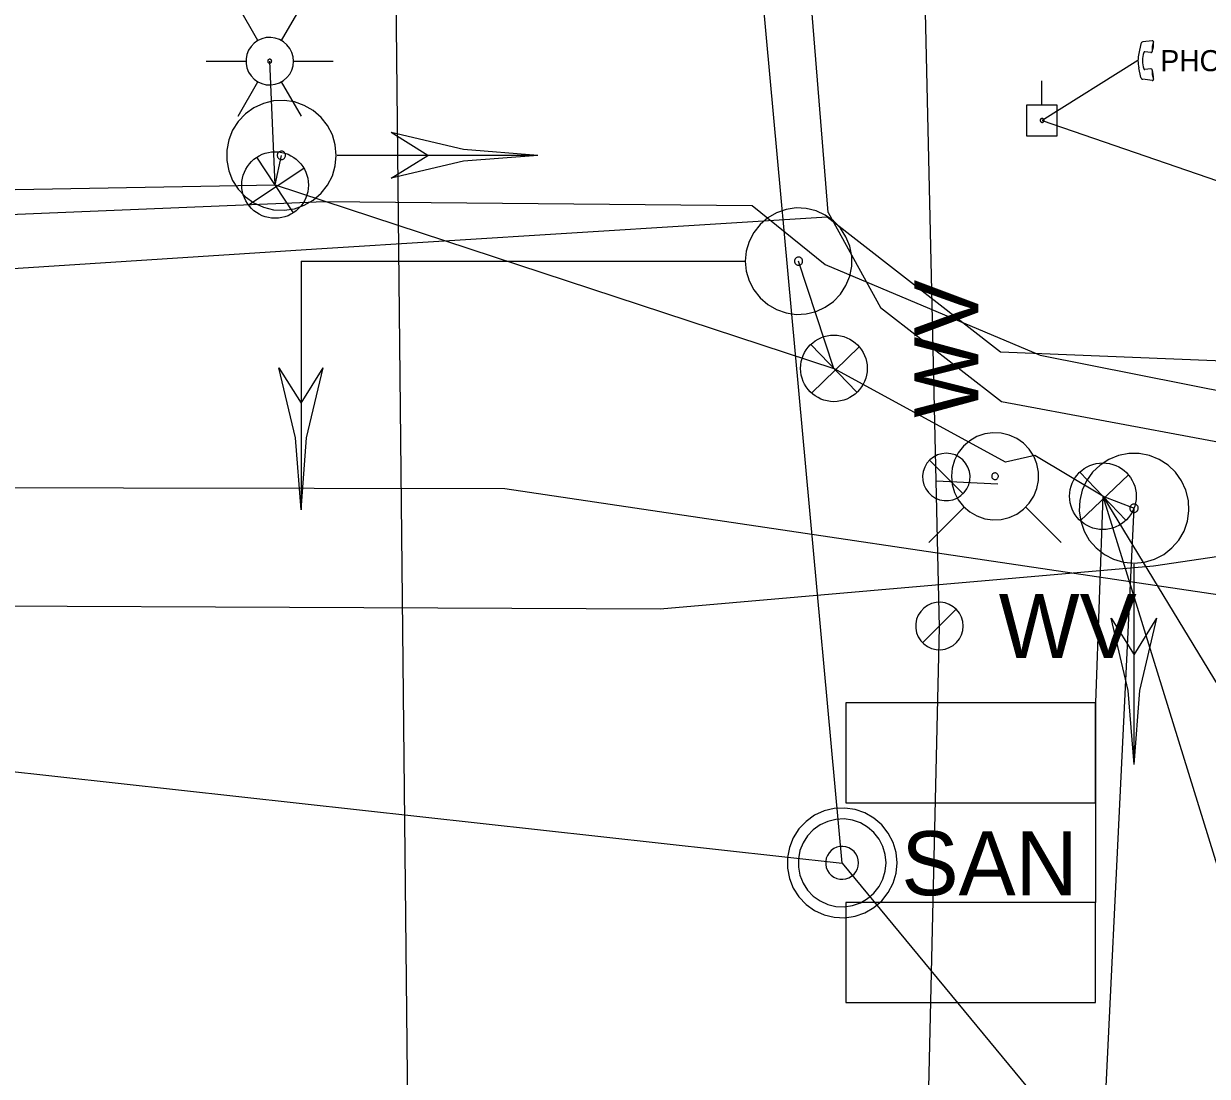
# Model space of a CAD drawing. Extents: x 596028 to 606371, y 330010 to 403088.
# Drawn here: x 605046.3 to 605117.4, y 332697.7 to 332760.9 of the extents above; entities that cross this region are included whole.
import ezdxf

# ---------------------------------------------------------------- set-up
doc = ezdxf.new("R2010")
doc.units = 0
for name, color, linetype in [('E_LTG', 7, 'Continuous'), ('E_LTG_CID', 7, 'Continuous'), ('E_SIG', 7, 'Continuous'), ('E_SIG_Conduit', 7, 'Continuous'), ('E_SIG_Loops', 7, 'Continuous'), ('E_UTL_E_UG', 7, 'Continuous'), ('E_UTL_FO_UG_MCI', 7, 'Continuous'), ('E_UTL_G_UG', 7, 'Continuous'), ('E_UTL_SAN_MH', 7, 'Continuous'), ('E_UTL_SAN_UG', 7, 'Continuous'), ('E_UTL_T', 7, 'Continuous'), ('E_UTL_T_UG', 7, 'Continuous'), ('E_UTL_TV_UG', 7, 'Continuous'), ('E_UTL_W', 7, 'Continuous'), ('E_UTL_W_UG', 7, 'Continuous'), ('E_UTL_WHydrant', 7, 'Continuous')]:
    doc.layers.add(name, color=color, linetype=linetype)

# ---------------------------------------------------------------- blocks, each defined once
blk = doc.blocks.new('_U303')
at = {"layer": 'E_SIG'}
for p, q in [((0, 6.1), (0, -6.1)), ((-6.09, 0.4), (6.1, 0.4))]:
    blk.add_line(p, q, dxfattribs=at)
blk.add_circle((0, 0.01), 6.1, dxfattribs=at)
blk = doc.blocks.new('_U304')
at = {"layer": 'E_SIG'}
for p, q in [((0, 6.1), (0, -6.1)), ((-6.09, 0.4), (6.1, 0.4))]:
    blk.add_line(p, q, dxfattribs=at)
blk.add_circle((0, 0.01), 6.1, dxfattribs=at)
blk = doc.blocks.new('_U309')
at = {"layer": 'E_SIG'}
for p, q in [((0, 6.1), (0, -6.1)), ((-6.09, 0.4), (6.1, 0.4))]:
    blk.add_line(p, q, dxfattribs=at)
blk.add_circle((0, 0.01), 6.1, dxfattribs=at)

msp = doc.modelspace()

# ---------------------------------------------------------------- linework, layer by layer
at = {"layer": 'E_LTG'}
for points in [[(605060.385, 332759.9), (605059.194, 332761.963)], [(605061.814, 332759.9), (605063.005, 332761.963)], [(605062.528, 332758.663), (605062.503, 332758.933), (605062.426, 332759.194), (605062.302, 332759.435), (605062.134, 332759.649), (605061.928, 332759.827), (605061.693, 332759.962), (605061.436, 332760.051), (605061.167, 332760.09), (605060.896, 332760.077), (605060.632, 332760.013), (605060.385, 332759.9), (605060.164, 332759.742), (605059.976, 332759.546), (605059.829, 332759.317), (605059.728, 332759.065), (605059.677, 332758.798), (605059.677, 332758.527), (605059.728, 332758.26), (605059.829, 332758.008), (605059.976, 332757.779), (605060.164, 332757.583), (605060.385, 332757.425), (605060.632, 332757.312), (605060.896, 332757.248), (605061.167, 332757.235), (605061.436, 332757.274), (605061.693, 332757.363), (605061.928, 332757.499), (605062.134, 332757.676), (605062.302, 332757.89), (605062.426, 332758.131), (605062.503, 332758.392), (605062.528, 332758.663)], [(605062.528, 332758.663), (605062.503, 332758.933), (605062.426, 332759.194), (605062.302, 332759.435), (605062.134, 332759.649), (605061.928, 332759.827), (605061.693, 332759.962), (605061.436, 332760.051), (605061.167, 332760.09), (605060.896, 332760.077), (605060.632, 332760.013), (605060.385, 332759.9), (605060.164, 332759.742), (605059.976, 332759.546), (605059.829, 332759.317), (605059.728, 332759.065), (605059.677, 332758.798), (605059.677, 332758.527), (605059.728, 332758.26), (605059.829, 332758.008), (605059.976, 332757.779), (605060.164, 332757.583), (605060.385, 332757.425), (605060.632, 332757.312), (605060.896, 332757.248), (605061.167, 332757.235), (605061.436, 332757.274), (605061.693, 332757.363), (605061.928, 332757.499), (605062.134, 332757.676), (605062.302, 332757.89), (605062.426, 332758.131), (605062.503, 332758.392), (605062.528, 332758.663)], [(605062.528, 332758.663), (605062.503, 332758.933), (605062.426, 332759.194), (605062.302, 332759.435), (605062.134, 332759.649), (605061.928, 332759.827), (605061.693, 332759.962), (605061.436, 332760.051), (605061.167, 332760.09), (605060.896, 332760.077), (605060.632, 332760.013), (605060.385, 332759.9), (605060.164, 332759.742), (605059.976, 332759.546), (605059.829, 332759.317), (605059.728, 332759.065), (605059.677, 332758.798), (605059.677, 332758.527), (605059.728, 332758.26), (605059.829, 332758.008), (605059.976, 332757.779), (605060.164, 332757.583), (605060.385, 332757.425), (605060.632, 332757.312), (605060.896, 332757.248), (605061.167, 332757.235), (605061.436, 332757.274), (605061.693, 332757.363), (605061.928, 332757.499), (605062.134, 332757.676), (605062.302, 332757.89), (605062.426, 332758.131), (605062.503, 332758.392), (605062.528, 332758.663)], [(605057.289, 332758.663), (605059.67, 332758.663)], [(605061.218, 332758.663), (605061.216, 332758.685), (605061.21, 332758.707), (605061.2, 332758.727), (605061.186, 332758.745), (605061.168, 332758.76), (605061.149, 332758.771), (605061.127, 332758.778), (605061.105, 332758.781), (605061.082, 332758.78), (605061.06, 332758.775), (605061.04, 332758.766), (605061.021, 332758.753), (605061.006, 332758.736), (605060.994, 332758.717), (605060.985, 332758.696), (605060.981, 332758.674), (605060.981, 332758.651), (605060.985, 332758.629), (605060.994, 332758.608), (605061.006, 332758.589), (605061.021, 332758.573), (605061.04, 332758.559), (605061.06, 332758.55), (605061.082, 332758.545), (605061.105, 332758.544), (605061.127, 332758.547), (605061.149, 332758.554), (605061.168, 332758.566), (605061.186, 332758.58), (605061.2, 332758.598), (605061.21, 332758.618), (605061.216, 332758.64), (605061.218, 332758.663)], [(605062.528, 332758.663), (605064.91, 332758.663)], [(605059.194, 332755.363), (605060.385, 332757.425)], [(605063.005, 332755.363), (605061.814, 332757.425)]]:
    msp.add_lwpolyline(points, dxfattribs=at)
at = {"layer": 'E_LTG_CID'}
msp.add_line((605061.421, 332751.222), (605061.099, 332758.663), dxfattribs=at)
at = {"layer": 'E_SIG'}
for points in [[(605065.101, 332753.004), (605065.041, 332753.629), (605064.864, 332754.23), (605064.577, 332754.788), (605064.189, 332755.281), (605063.715, 332755.692), (605063.172, 332756.006), (605062.579, 332756.211), (605061.958, 332756.3), (605061.331, 332756.27), (605060.722, 332756.122), (605060.151, 332755.862), (605059.64, 332755.498), (605059.207, 332755.044), (605058.868, 332754.516), (605058.635, 332753.934), (605058.516, 332753.318), (605058.516, 332752.69), (605058.635, 332752.074), (605058.868, 332751.492), (605059.207, 332750.964), (605059.64, 332750.51), (605060.151, 332750.146), (605060.722, 332749.885), (605061.331, 332749.738), (605061.958, 332749.708), (605062.579, 332749.797), (605063.172, 332750.002), (605063.715, 332750.316), (605064.189, 332750.727), (605064.577, 332751.22), (605064.864, 332751.778), (605065.041, 332752.379), (605065.101, 332753.004)], [(605070.601, 332753.003), (605068.401, 332754.38)], [(605077.201, 332753.004), (605072.747, 332753.35), (605068.401, 332754.379)], [(605062.053, 332753.004), (605062.049, 332753.052), (605062.035, 332753.098), (605062.013, 332753.14), (605061.984, 332753.178), (605061.947, 332753.21), (605061.906, 332753.234), (605061.86, 332753.249), (605061.813, 332753.256), (605061.765, 332753.254), (605061.718, 332753.243), (605061.675, 332753.223), (605061.636, 332753.195), (605061.602, 332753.16), (605061.577, 332753.12), (605061.559, 332753.075), (605061.55, 332753.028), (605061.55, 332752.98), (605061.559, 332752.933), (605061.577, 332752.888), (605061.602, 332752.848), (605061.636, 332752.813), (605061.675, 332752.785), (605061.718, 332752.765), (605061.765, 332752.754), (605061.813, 332752.752), (605061.86, 332752.759), (605061.906, 332752.774), (605061.947, 332752.798), (605061.984, 332752.83), (605062.013, 332752.868), (605062.035, 332752.91), (605062.049, 332752.956), (605062.053, 332753.004)], [(605077.2, 332753.003), (605065.159, 332753.003)], [(605077.201, 332753.004), (605072.747, 332752.658), (605068.401, 332751.629)], [(605068.401, 332751.631), (605070.601, 332753.003)], [(605089.674, 332746.644), (605089.732, 332746.038), (605089.904, 332745.454), (605090.183, 332744.912), (605090.559, 332744.434), (605091.019, 332744.035), (605091.547, 332743.731), (605092.122, 332743.531), (605092.725, 332743.445), (605093.333, 332743.474), (605093.925, 332743.617), (605094.479, 332743.87), (605094.975, 332744.223), (605095.395, 332744.664), (605095.724, 332745.176), (605095.951, 332745.742), (605096.066, 332746.34), (605096.066, 332746.948), (605095.951, 332747.546), (605095.724, 332748.112), (605095.395, 332748.624), (605094.975, 332749.065), (605094.479, 332749.418), (605093.925, 332749.671), (605093.333, 332749.814), (605092.725, 332749.843), (605092.122, 332749.757), (605091.547, 332749.558), (605091.019, 332749.253), (605090.559, 332748.854), (605090.183, 332748.376), (605089.904, 332747.834), (605089.732, 332747.25), (605089.674, 332746.644)], [(605062.983, 332746.643), (605089.622, 332746.643)], [(605062.983, 332746.643), (605062.983, 332731.697)], [(605070.457, 332746.643), (605070.457, 332746.643)], [(605092.632, 332746.644), (605092.637, 332746.598), (605092.65, 332746.553), (605092.671, 332746.512), (605092.7, 332746.475), (605092.735, 332746.444), (605092.776, 332746.421), (605092.82, 332746.406), (605092.866, 332746.399), (605092.912, 332746.402), (605092.957, 332746.413), (605093, 332746.432), (605093.038, 332746.459), (605093.07, 332746.493), (605093.095, 332746.532), (605093.112, 332746.575), (605093.121, 332746.621), (605093.121, 332746.667), (605093.112, 332746.713), (605093.095, 332746.756), (605093.07, 332746.795), (605093.038, 332746.829), (605093, 332746.856), (605092.957, 332746.876), (605092.912, 332746.886), (605092.866, 332746.889), (605092.82, 332746.882), (605092.776, 332746.867), (605092.735, 332746.844), (605092.7, 332746.813), (605092.671, 332746.776), (605092.65, 332746.735), (605092.637, 332746.69), (605092.632, 332746.644)], [(605061.646, 332740.237), (605062.983, 332738.102)], [(605062.983, 332731.697), (605062.648, 332736.019), (605061.649, 332740.238)], [(605062.983, 332731.697), (605063.319, 332736.019), (605064.318, 332740.238)], [(605062.983, 332738.102), (605064.32, 332740.237)], [(605113.034, 332728.494), (605113.658, 332728.554), (605114.26, 332728.73), (605114.818, 332729.018), (605115.311, 332729.406), (605115.722, 332729.88), (605116.036, 332730.423), (605116.241, 332731.016), (605116.33, 332731.637), (605116.3, 332732.264), (605116.152, 332732.873), (605115.892, 332733.444), (605115.528, 332733.955), (605115.074, 332734.388), (605114.546, 332734.727), (605113.964, 332734.96), (605113.348, 332735.079), (605112.72, 332735.079), (605112.104, 332734.96), (605111.522, 332734.727), (605110.994, 332734.388), (605110.54, 332733.955), (605110.176, 332733.444), (605109.915, 332732.873), (605109.767, 332732.264), (605109.738, 332731.637), (605109.827, 332731.016), (605110.032, 332730.423), (605110.346, 332729.88), (605110.757, 332729.406), (605111.25, 332729.018), (605111.807, 332728.73), (605112.409, 332728.554), (605113.034, 332728.494)], [(605113.034, 332731.542), (605113.082, 332731.546), (605113.128, 332731.56), (605113.17, 332731.582), (605113.208, 332731.611), (605113.239, 332731.648), (605113.263, 332731.689), (605113.279, 332731.734), (605113.286, 332731.782), (605113.284, 332731.83), (605113.272, 332731.877), (605113.252, 332731.92), (605113.225, 332731.959), (605113.19, 332731.992), (605113.15, 332732.018), (605113.105, 332732.036), (605113.058, 332732.045), (605113.01, 332732.045), (605112.963, 332732.036), (605112.918, 332732.018), (605112.878, 332731.992), (605112.843, 332731.959), (605112.815, 332731.92), (605112.795, 332731.877), (605112.784, 332731.83), (605112.782, 332731.782), (605112.789, 332731.734), (605112.804, 332731.689), (605112.828, 332731.648), (605112.86, 332731.611), (605112.897, 332731.582), (605112.94, 332731.56), (605112.986, 332731.546), (605113.034, 332731.542)], [(605113.033, 332716.395), (605113.033, 332728.436)], [(605113.034, 332716.394), (605112.688, 332720.847), (605111.659, 332725.194)], [(605111.661, 332725.194), (605113.033, 332722.993)], [(605113.033, 332722.993), (605114.41, 332725.194)], [(605113.034, 332716.394), (605113.38, 332720.847), (605114.409, 332725.194)]]:
    msp.add_lwpolyline(points, dxfattribs=at)
at = {"layer": 'E_SIG_Conduit'}
for p, q in [((605061.421, 332751.222), (605061.801, 332753.004)), ((605094.998, 332740.201), (605092.877, 332746.644)), ((605111.161, 332732.518), (605113.034, 332731.794))]:
    msp.add_line(p, q, dxfattribs=at)
for points in [[(605007.43, 332680.058), (605008.376, 332738.509), (605017.545, 332739.78), (605013.444, 332750.366), (605061.421, 332751.222), (605094.998, 332740.201)], [(605111.161, 332732.518), (605107.07, 332734.971), (605105.315, 332734.569), (605094.998, 332740.201)], [(605008.763, 332680.663), (605025.688, 332657.851), (605055.914, 332657.363), (605097.604, 332661.293), (605110.543, 332680.066), (605113.034, 332731.794)]]:
    msp.add_lwpolyline(points, dxfattribs=at)
at = {"layer": 'E_SIG_Loops'}
for p, q in [((605111.161, 332732.518), (605110.716, 332720.094)), ((605111.161, 332732.518), (605118.716, 332720.094)), ((605111.161, 332732.518), (605118.716, 332708.094)), ((605110.716, 332720.094), (605110.716, 332708.094))]:
    msp.add_line(p, q, dxfattribs=at)
for points in [[(605110.716, 332714.094), (605110.716, 332720.094), (605095.716, 332720.094), (605095.716, 332714.094), (605110.716, 332714.094)], [(605110.716, 332702.094), (605110.716, 332708.094), (605095.716, 332708.094), (605095.716, 332702.094), (605110.716, 332702.094)]]:
    msp.add_lwpolyline(points, dxfattribs=at)
at = {"layer": 'E_UTL_E_UG'}
msp.add_lwpolyline([(605006.489, 332733.094), (605075.221, 332732.971), (605164.121, 332719.76)], dxfattribs=at)
at = {"layer": 'E_UTL_FO_UG_MCI'}
msp.add_lwpolyline([(604825.965, 332739.777), (604920.611, 332734.359), (604934.013, 332733.307), (604965.466, 332732.978), (605000.461, 332732.523), (605007.071, 332734.658), (605013.891, 332743.485), (605017.003, 332744.164), (605019.168, 332746.545), (605020.116, 332744.843), (605024.63, 332744.843), (605063.908, 332747.381), (605094.592, 332749.315), (605105.01, 332741.186), (605136.253, 332739.937), (605148.9, 332737.411), (605162.548, 332734.785), (605195.984, 332734.314), (605235.108, 332733.745)], dxfattribs=at)
at = {"layer": 'E_UTL_G_UG'}
msp.add_lwpolyline([(605069.907, 332651.643), (605069.52, 332684.313), (605067.35, 332890.684)], dxfattribs=at)
at = {"layer": 'E_UTL_SAN_MH'}
for points in [[(605098.791, 332710.481), (605098.732, 332711.105), (605098.555, 332711.707), (605098.267, 332712.265), (605097.88, 332712.758), (605097.405, 332713.169), (605096.862, 332713.483), (605096.269, 332713.688), (605095.648, 332713.777), (605095.022, 332713.747), (605094.412, 332713.599), (605093.841, 332713.339), (605093.33, 332712.975), (605092.897, 332712.521), (605092.558, 332711.993), (605092.325, 332711.411), (605092.206, 332710.795), (605092.206, 332710.167), (605092.325, 332709.551), (605092.558, 332708.969), (605092.897, 332708.441), (605093.33, 332707.987), (605093.841, 332707.623), (605094.412, 332707.362), (605095.022, 332707.214), (605095.648, 332707.185), (605096.269, 332707.274), (605096.862, 332707.479), (605097.405, 332707.793), (605097.88, 332708.204), (605098.267, 332708.697), (605098.555, 332709.254), (605098.732, 332709.856), (605098.791, 332710.481)], [(605098.131, 332710.481), (605098.084, 332710.98), (605097.942, 332711.462), (605097.712, 332711.908), (605097.402, 332712.303), (605097.023, 332712.631), (605096.588, 332712.882), (605096.114, 332713.046), (605095.617, 332713.118), (605095.116, 332713.094), (605094.628, 332712.976), (605094.171, 332712.767), (605093.762, 332712.476), (605093.416, 332712.113), (605093.145, 332711.691), (605092.958, 332711.225), (605092.863, 332710.732), (605092.863, 332710.23), (605092.958, 332709.737), (605093.145, 332709.271), (605093.416, 332708.849), (605093.762, 332708.486), (605094.171, 332708.195), (605094.628, 332707.986), (605095.116, 332707.868), (605095.617, 332707.844), (605096.114, 332707.915), (605096.588, 332708.079), (605097.023, 332708.33), (605097.402, 332708.659), (605097.712, 332709.054), (605097.942, 332709.5), (605098.084, 332709.981), (605098.131, 332710.481)], [(605096.481, 332710.481), (605096.463, 332710.668), (605096.41, 332710.849), (605096.324, 332711.016), (605096.208, 332711.164), (605096.065, 332711.287), (605095.902, 332711.381), (605095.725, 332711.443), (605095.538, 332711.47), (605095.35, 332711.461), (605095.167, 332711.416), (605094.996, 332711.338), (605094.843, 332711.229), (605094.713, 332711.093), (605094.611, 332710.934), (605094.541, 332710.76), (605094.506, 332710.575), (605094.506, 332710.387), (605094.541, 332710.202), (605094.611, 332710.027), (605094.713, 332709.869), (605094.843, 332709.733), (605094.996, 332709.623), (605095.167, 332709.545), (605095.35, 332709.501), (605095.538, 332709.492), (605095.725, 332709.519), (605095.902, 332709.58), (605096.065, 332709.674), (605096.208, 332709.798), (605096.324, 332709.946), (605096.41, 332710.113), (605096.463, 332710.293), (605096.481, 332710.481)]]:
    msp.add_lwpolyline(points, dxfattribs=at)
at = {"layer": 'E_UTL_SAN_UG'}
for p, q in [((605095.505, 332710.464), (605061.781, 333078.09)), ((604993.056, 332721.79), (605095.505, 332710.464)), ((605095.505, 332710.464), (605139.844, 332656.789))]:
    msp.add_line(p, q, dxfattribs=at)
at = {"layer": 'E_UTL_T'}
for points in [[(605113.44, 332759.708), (605113.316, 332759.134)], [(605114.128, 332759.895), (605113.556, 332759.816)], [(605113.269, 332758.695), (605107.508, 332755.103)], [(605114.05, 332759.185), (605113.69, 332759.234)], [(605113.44, 332757.682), (605113.316, 332758.256)], [(605114.05, 332758.205), (605113.69, 332758.156)], [(605107.492, 332756.024), (605107.492, 332757.479)], [(605114.128, 332757.495), (605113.556, 332757.574)], [(605108.414, 332756.024), (605106.57, 332756.024)], [(605106.57, 332756.024), (605106.57, 332754.179)], [(605108.414, 332754.179), (605108.414, 332756.024)], [(605107.627, 332755.103), (605107.625, 332755.126), (605107.619, 332755.147), (605107.608, 332755.167), (605107.594, 332755.185), (605107.577, 332755.2), (605107.558, 332755.211), (605107.536, 332755.219), (605107.514, 332755.222), (605107.491, 332755.221), (605107.469, 332755.216), (605107.448, 332755.206), (605107.43, 332755.193), (605107.414, 332755.177), (605107.402, 332755.158), (605107.394, 332755.137), (605107.389, 332755.114), (605107.389, 332755.092), (605107.394, 332755.069), (605107.402, 332755.048), (605107.414, 332755.029), (605107.43, 332755.013), (605107.448, 332755), (605107.469, 332754.99), (605107.491, 332754.985), (605107.514, 332754.984), (605107.536, 332754.987), (605107.558, 332754.995), (605107.577, 332755.006), (605107.594, 332755.021), (605107.608, 332755.039), (605107.619, 332755.059), (605107.625, 332755.08), (605107.627, 332755.103)], [(605107.508, 332755.103), (605176.941, 332731.201)], [(605106.57, 332754.179), (605108.414, 332754.179)]]:
    msp.add_lwpolyline(points, dxfattribs=at)
for centre, radius, start, end in [((605113.575, 332759.679), 0.139, 97.81529, 167.80472), ((605115.218, 332759.385), 1.1, 156.92275, 187.38366), ((605112.772, 332759.722), 1.438, 340.55958, 3.74683), ((605114.137, 332759.826), 0.0693, 352.19703, 97.81995), ((605115.347, 332758.695), 2.078, 167.80315, 192.18987), ((605115.347, 332758.695), 1.801, 164.24015, 195.74477), ((605113.68, 332759.165), 0.0693, 82.19265, 164.24015), ((605114.059, 332759.253), 0.0693, 262.19702, 352.19717), ((605113.68, 332758.225), 0.0693, 195.74477, 277.80892), ((605114.059, 332758.137), 0.0693, 7.90399, 97.80458), ((605115.259, 332758.011), 1.14, 173.14925, 202.53133), ((605112.129, 332757.58), 2.077, 359.83887, 15.84171), ((605113.575, 332757.711), 0.139, 192.196, 262.17939), ((605114.137, 332757.564), 0.0693, 262.18927, 7.81656)]:
    msp.add_arc(centre, radius, start, end, dxfattribs=at)
at = {"layer": 'E_UTL_T_UG'}
msp.add_lwpolyline([(604626.24, 332752.959), (604667.794, 332752.275), (604716.523, 332751.286), (604772.473, 332750.78), (604802.275, 332745.127), (604821.107, 332741.835), (604839.236, 332737.015), (604851.386, 332734.26), (604870.699, 332730.275), (604882.931, 332728.13), (604900.247, 332727.489), (604950.981, 332727.08), (604995.392, 332726.287), (605022.191, 332726.026), (605084.559, 332725.744), (605114.198, 332728.338), (605148.015, 332733.348)], dxfattribs=at)
at = {"layer": 'E_UTL_TV_UG'}
for points in [[(605094.663, 332749.565), (605093.186, 332767.662), (605089.64, 332794.29), (605088.03, 332813.98), (605084.1, 332862.98), (605082.36, 332885.78), (605078.4, 332931.64), (605073.44, 332982.369), (605071.45, 333013.369), (605067.62, 333058.929), (605065.49, 333085.159), (605061.42, 333132.769), (605058.07, 333175.199), (605056.52, 333223.419), (605057.28, 333240.579), (605057.66, 333247.689), (605057.53, 333257.639), (605054.7, 333270.549), (605051.63, 333282.989), (605048.15, 333292.969), (605046.32, 333306.439), (605046.78, 333343.599), (605047.66, 333380.139), (605052.04, 333566.048)], [(604885.989, 332737.633), (604916.228, 332736.122), (604975.491, 332735.631), (604992.966, 332736.893), (605003.39, 332739.416), (605012.687, 332741.023), (605017.027, 332745.713), (605042.522, 332749.334), (605064.377, 332750.232), (605090.092, 332749.989), (605094.482, 332746.45), (605107.382, 332741.003), (605124.946, 332737.504)], [(605094.663, 332749.565), (605097.808, 332743.855), (605105.065, 332738.206), (605123.764, 332734.728), (605152.114, 332736.192), (605171.904, 332736.596), (605176.941, 332731.201)]]:
    msp.add_lwpolyline(points, dxfattribs=at)
at = {"layer": 'E_UTL_W'}
for points in [[(605101.753, 332735.098), (605101.483, 332735.072), (605101.223, 332734.995), (605100.982, 332734.871), (605100.769, 332734.704), (605100.591, 332734.499), (605100.456, 332734.264), (605100.367, 332734.008), (605100.328, 332733.739), (605100.341, 332733.469), (605100.405, 332733.205), (605100.518, 332732.959), (605100.675, 332732.738), (605100.871, 332732.551), (605101.099, 332732.404), (605101.351, 332732.303), (605101.617, 332732.252), (605101.888, 332732.252), (605102.154, 332732.303), (605102.406, 332732.404), (605102.634, 332732.551), (605102.83, 332732.738), (605102.987, 332732.959), (605103.1, 332733.205), (605103.164, 332733.469), (605103.177, 332733.739), (605103.138, 332734.008), (605103.05, 332734.264), (605102.914, 332734.499), (605102.737, 332734.704), (605102.523, 332734.871), (605102.283, 332734.995), (605102.022, 332735.072), (605101.753, 332735.098)], [(605102.761, 332732.663), (605100.745, 332734.68)], [(605102.763, 332724.717), (605102.738, 332724.986), (605102.661, 332725.247), (605102.537, 332725.487), (605102.37, 332725.701), (605102.165, 332725.878), (605101.93, 332726.014), (605101.674, 332726.102), (605101.405, 332726.141), (605101.135, 332726.128), (605100.871, 332726.064), (605100.625, 332725.951), (605100.404, 332725.794), (605100.217, 332725.598), (605100.07, 332725.37), (605099.969, 332725.118), (605099.918, 332724.852), (605099.918, 332724.581), (605099.969, 332724.315), (605100.07, 332724.063), (605100.217, 332723.835), (605100.404, 332723.639), (605100.625, 332723.482), (605100.871, 332723.369), (605101.135, 332723.305), (605101.405, 332723.292), (605101.674, 332723.331), (605101.93, 332723.42), (605102.165, 332723.555), (605102.37, 332723.733), (605102.537, 332723.946), (605102.661, 332724.187), (605102.738, 332724.447), (605102.763, 332724.717)], [(605100.329, 332723.708), (605102.346, 332725.725)]]:
    msp.add_lwpolyline(points, dxfattribs=at)
at = {"layer": 'E_UTL_W_UG'}
msp.add_line((605101.137, 332733.44), (605104.845, 332733.268), dxfattribs=at)
msp.add_lwpolyline([(605099.885, 332661.458), (605101.335, 332724.652), (605100.202, 332774.816), (605098.774, 332797.727), (605095.426, 332832.089)], dxfattribs=at)
at = {"layer": 'E_UTL_WHydrant'}
for points in [[(605102.056, 332733.716), (605102.104, 332733.22), (605102.244, 332732.741), (605102.473, 332732.298), (605102.781, 332731.906), (605103.158, 332731.58), (605103.589, 332731.33), (605104.061, 332731.167), (605104.554, 332731.096), (605105.052, 332731.12), (605105.537, 332731.237), (605105.99, 332731.445), (605106.397, 332731.734), (605106.741, 332732.095), (605107.01, 332732.514), (605107.196, 332732.977), (605107.29, 332733.467), (605107.29, 332733.965), (605107.196, 332734.455), (605107.01, 332734.918), (605106.741, 332735.337), (605106.397, 332735.698), (605105.99, 332735.987), (605105.537, 332736.195), (605105.052, 332736.312), (605104.554, 332736.336), (605104.061, 332736.265), (605103.589, 332736.102), (605103.158, 332735.852), (605102.781, 332735.526), (605102.473, 332735.134), (605102.244, 332734.691), (605102.104, 332734.212), (605102.056, 332733.716)], [(605104.478, 332733.716), (605104.482, 332733.678), (605104.493, 332733.641), (605104.51, 332733.608), (605104.534, 332733.578), (605104.563, 332733.553), (605104.596, 332733.534), (605104.632, 332733.521), (605104.669, 332733.516), (605104.708, 332733.517), (605104.745, 332733.526), (605104.779, 332733.542), (605104.81, 332733.564), (605104.837, 332733.592), (605104.857, 332733.624), (605104.871, 332733.659), (605104.879, 332733.697), (605104.879, 332733.735), (605104.871, 332733.773), (605104.857, 332733.808), (605104.837, 332733.84), (605104.81, 332733.868), (605104.779, 332733.89), (605104.745, 332733.906), (605104.708, 332733.915), (605104.669, 332733.916), (605104.632, 332733.911), (605104.596, 332733.898), (605104.563, 332733.879), (605104.534, 332733.854), (605104.51, 332733.824), (605104.493, 332733.791), (605104.482, 332733.754), (605104.478, 332733.716)], [(605102.843, 332731.881), (605100.701, 332729.739)], [(605106.513, 332731.881), (605108.656, 332729.739)]]:
    msp.add_lwpolyline(points, dxfattribs=at)

# ---------------------------------------------------------------- block references
at = {"layer": 'E_SIG', "xscale": 0.32808333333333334}
for name, p, yscale, rotation in [('_U309', (605061.418, 332751.224), 0.3280833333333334, -146.58217688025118), ('_U304', (605094.995, 332740.203), 0.3280833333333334, -135.9656687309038), ('_U303', (605111.158, 332732.52), 0.32808333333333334, -136.27764087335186)]:
    msp.add_blockref(name, p, dxfattribs=dict(at, yscale=yscale, rotation=rotation))

# ---------------------------------------------------------------- texts
at = {"layer": 'E_UTL_SAN_MH'}
msp.add_text('SAN', height=3.8491, dxfattribs=at).set_placement((605099.055, 332708.535))
at = {"layer": 'E_UTL_T'}
msp.add_text('PHONE', height=1.2671, dxfattribs=at).set_placement((605114.62, 332758.061))
at = {"layer": 'E_UTL_W'}
msp.add_text('WV', height=3.85, rotation=90, dxfattribs=at).set_placement((605103.678, 332737.236))
msp.add_text('WV', height=3.85, dxfattribs=at).set_placement((605104.902, 332722.791))

doc.saveas('drawing.dxf')
